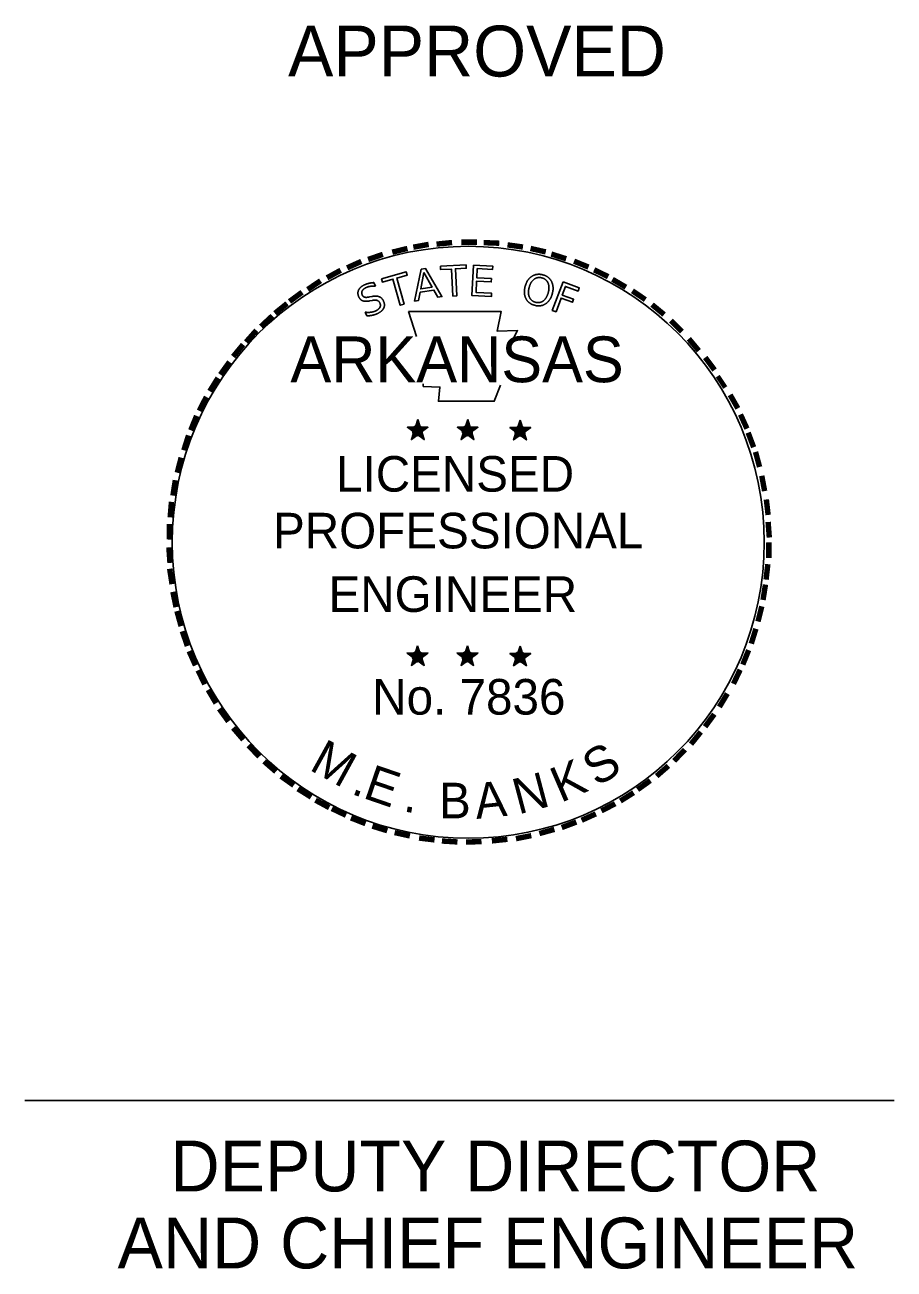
# Model space of a CAD drawing. Extents: x -0.68 to 1.92, y 0 to 0.95.
# Drawn here: x 1.7484 to 1.9193, y 0.0415 to 0.2862 of the extents above; entities that cross this region are included whole.
import ezdxf

# ---------------------------------------------------------------- set-up
doc = ezdxf.new("R2010")
doc.units = 0
doc.layers.add('SHET_Stamp-PE-Chief-Eng', color=7, linetype='Continuous')

msp = doc.modelspace()

# ---------------------------------------------------------------- linework, layer by layer
at = {"layer": 'SHET_Stamp-PE-Chief-Eng'}
for p, q in [((1.81706, 0.23552), (1.81734, 0.23483)), ((1.85009, 0.23645), (1.85009, 0.23645)), ((1.85025, 0.23705), (1.85025, 0.23705)), ((1.81617, 0.23269), (1.81666, 0.23279)), ((1.81673, 0.23202), (1.81623, 0.23192)), ((1.81562, 0.22896), (1.81532, 0.2297)), ((1.82568, 0.20858), (1.82544, 0.20707)), ((1.82568, 0.20641), (1.82568, 0.20858)), ((1.82568, 0.20858), (1.82598, 0.20713)), ((1.83551, 0.20858), (1.83527, 0.20707)), ((1.83551, 0.20641), (1.83551, 0.20858)), ((1.83551, 0.20858), (1.83576, 0.20713)), ((1.84583, 0.20846), (1.84559, 0.20701)), ((1.84583, 0.20635), (1.84583, 0.20846)), ((1.84583, 0.20846), (1.84608, 0.20701)), ((1.82363, 0.20707), (1.82568, 0.20641)), ((1.82363, 0.20707), (1.82513, 0.20683)), ((1.82363, 0.20707), (1.82501, 0.20635)), ((1.82441, 0.20466), (1.82568, 0.20641)), ((1.82441, 0.20466), (1.82513, 0.20611)), ((1.82441, 0.20466), (1.82562, 0.20593)), ((1.82694, 0.20466), (1.82562, 0.20593)), ((1.82767, 0.20707), (1.82568, 0.20641)), ((1.82694, 0.20466), (1.82568, 0.20641)), ((1.82767, 0.20707), (1.82604, 0.20677)), ((1.82694, 0.20466), (1.8261, 0.20635)), ((1.82767, 0.20707), (1.82652, 0.20647)), ((1.83346, 0.20707), (1.83551, 0.20641)), ((1.83346, 0.20707), (1.83491, 0.20683)), ((1.83346, 0.20707), (1.83479, 0.20635)), ((1.83419, 0.20466), (1.83551, 0.20641)), ((1.83419, 0.20466), (1.83497, 0.20611)), ((1.83419, 0.20466), (1.83545, 0.20593)), ((1.83672, 0.20466), (1.83545, 0.20593)), ((1.83751, 0.20707), (1.83551, 0.20641)), ((1.83672, 0.20466), (1.83551, 0.20641)), ((1.83751, 0.20707), (1.83582, 0.20677)), ((1.83672, 0.20466), (1.83588, 0.20635)), ((1.83751, 0.20707), (1.8363, 0.20647)), ((1.84378, 0.20701), (1.84583, 0.20635)), ((1.84378, 0.20701), (1.84523, 0.20671)), ((1.84378, 0.20701), (1.84517, 0.20629)), ((1.84451, 0.2046), (1.84583, 0.20635)), ((1.84451, 0.2046), (1.84529, 0.20605)), ((1.84451, 0.2046), (1.84583, 0.20587)), ((1.84789, 0.20701), (1.84583, 0.20635)), ((1.84704, 0.2046), (1.84583, 0.20635)), ((1.84704, 0.2046), (1.84583, 0.20587)), ((1.84789, 0.20701), (1.84614, 0.20671)), ((1.84704, 0.2046), (1.84626, 0.20629)), ((1.84789, 0.20701), (1.84662, 0.20641)), ((1.82562, 0.1641), (1.82538, 0.16266)), ((1.82562, 0.16199), (1.82562, 0.1641)), ((1.82562, 0.1641), (1.82592, 0.16266)), ((1.83545, 0.1641), (1.83521, 0.16266)), ((1.83545, 0.16199), (1.83545, 0.1641)), ((1.83545, 0.1641), (1.8357, 0.16266)), ((1.84583, 0.16404), (1.84559, 0.1626)), ((1.84583, 0.16193), (1.84583, 0.16404)), ((1.84583, 0.16404), (1.84608, 0.1626)), ((1.82357, 0.16266), (1.82562, 0.16199)), ((1.82357, 0.16266), (1.82513, 0.16235)), ((1.82357, 0.16266), (1.82501, 0.16193)), ((1.82441, 0.16024), (1.82562, 0.16199)), ((1.82441, 0.16024), (1.82513, 0.16169)), ((1.82441, 0.16024), (1.82562, 0.16157)), ((1.82767, 0.16266), (1.82562, 0.16199)), ((1.82694, 0.16024), (1.82562, 0.16199)), ((1.82694, 0.16024), (1.82562, 0.16151)), ((1.82767, 0.16266), (1.82598, 0.16235)), ((1.82694, 0.16024), (1.8261, 0.16193)), ((1.82767, 0.16266), (1.82652, 0.16205)), ((1.8334, 0.16266), (1.83545, 0.16199)), ((1.8334, 0.16266), (1.83491, 0.16235)), ((1.8334, 0.16266), (1.83479, 0.16193)), ((1.83419, 0.16024), (1.83545, 0.16199)), ((1.83419, 0.16024), (1.83491, 0.16169)), ((1.83419, 0.16024), (1.83545, 0.16157)), ((1.83751, 0.16266), (1.83545, 0.16199)), ((1.83666, 0.16024), (1.83545, 0.16199)), ((1.83666, 0.16024), (1.83545, 0.16151)), ((1.83751, 0.16266), (1.83576, 0.16235)), ((1.83666, 0.16024), (1.83588, 0.16193)), ((1.83751, 0.16266), (1.83624, 0.16205)), ((1.84378, 0.1626), (1.84583, 0.16193)), ((1.84378, 0.1626), (1.84523, 0.16229)), ((1.84378, 0.1626), (1.84517, 0.16187)), ((1.84451, 0.16018), (1.84583, 0.16193)), ((1.84451, 0.16018), (1.84529, 0.16163)), ((1.84451, 0.16018), (1.84583, 0.16151)), ((1.84789, 0.1626), (1.84583, 0.16193)), ((1.84704, 0.16018), (1.84583, 0.16193)), ((1.84789, 0.1626), (1.84614, 0.16229)), ((1.84704, 0.16018), (1.8462, 0.16187)), ((1.84789, 0.1626), (1.84662, 0.16199)), ((1.84704, 0.16018), (1.84583, 0.16145)), ((1.74841, 0.07469), (1.91934, 0.07469))]:
    msp.add_line(p, q, dxfattribs=at)
for points in [[(1.81855, 0.23625), (1.82342, 0.23762), (1.82359, 0.237), (1.82153, 0.23642), (1.82298, 0.23129), (1.82223, 0.23108), (1.82078, 0.23621), (1.81873, 0.23563)], [(1.82632, 0.23814), (1.82504, 0.23187), (1.82584, 0.232), (1.82613, 0.23361), (1.82884, 0.23406), (1.82964, 0.23263), (1.83043, 0.23276), (1.82721, 0.23829)], [(1.82688, 0.2375), (1.8285, 0.23465), (1.82626, 0.23428)], [(1.83012, 0.23872), (1.83516, 0.23899), (1.8352, 0.23835), (1.83306, 0.23823), (1.83335, 0.23291), (1.83258, 0.23286), (1.83229, 0.23819), (1.83015, 0.23807)], [(1.83664, 0.23896), (1.8404, 0.23876), (1.84037, 0.23811), (1.83738, 0.23827), (1.83729, 0.23645), (1.84015, 0.2363), (1.84011, 0.23566), (1.83725, 0.23581), (1.83714, 0.23359), (1.8402, 0.23343), (1.84016, 0.23278), (1.83633, 0.23298)], [(1.85423, 0.23566), (1.85743, 0.23446), (1.8572, 0.23385), (1.85472, 0.23478), (1.85409, 0.23308), (1.85632, 0.23225), (1.8561, 0.23164), (1.85386, 0.23248), (1.85286, 0.22979), (1.85213, 0.23006)]]:
    msp.add_lwpolyline(points, close=True, dxfattribs=at)
for points in [[(1.82387, 0.22982), (1.82544, 0.22494)], [(1.84445, 0.22445), (1.84529, 0.22608), (1.84131, 0.22596), (1.84209, 0.22982), (1.82387, 0.22982)], [(1.82676, 0.21564), (1.82676, 0.2151), (1.83002, 0.21498), (1.82972, 0.2122), (1.8407, 0.2122), (1.84191, 0.21534)], [(1.82568, 0.20858), (1.82694, 0.20466), (1.82363, 0.20707), (1.82767, 0.20707), (1.82441, 0.20466), (1.82568, 0.20858)], [(1.83551, 0.20858), (1.83672, 0.20466), (1.83346, 0.20707), (1.83751, 0.20707), (1.83419, 0.20466), (1.83551, 0.20858)], [(1.84583, 0.20846), (1.84704, 0.2046), (1.84378, 0.20701), (1.84789, 0.20701), (1.84451, 0.2046), (1.84583, 0.20846)], [(1.82562, 0.1641), (1.82694, 0.16024), (1.82357, 0.16266), (1.82767, 0.16266), (1.82441, 0.16024), (1.82562, 0.1641)], [(1.83545, 0.1641), (1.83666, 0.16024), (1.8334, 0.16266), (1.83751, 0.16266), (1.83419, 0.16024), (1.83545, 0.1641)], [(1.84583, 0.16404), (1.84704, 0.16018), (1.84378, 0.1626), (1.84789, 0.1626), (1.84451, 0.16018), (1.84583, 0.16404)]]:
    msp.add_lwpolyline(points, dxfattribs=at)
for centre, radius in [((1.8356, 0.18445), 0.05821), ((1.82562, 0.2064), 0.00101), ((1.82562, 0.2064), 0.000848), ((1.82562, 0.2064), 0.000679), ((1.82562, 0.2064), 0.000581), ((1.82562, 0.2064), 0.000438), ((1.82562, 0.2064), 0.000291), ((1.82562, 0.2064), 0.000174), ((1.83542, 0.2064), 0.00101), ((1.83542, 0.2064), 0.000848), ((1.83542, 0.2064), 0.000679), ((1.83542, 0.2064), 0.000581), ((1.83542, 0.2064), 0.000438), ((1.83542, 0.2064), 0.000291), ((1.83542, 0.2064), 0.000174), ((1.84577, 0.20633), 0.00101), ((1.84577, 0.20633), 0.000848), ((1.84577, 0.20633), 0.000679), ((1.84577, 0.20633), 0.000581), ((1.84577, 0.20633), 0.000438), ((1.84577, 0.20633), 0.000291), ((1.84577, 0.20633), 0.000174), ((1.8256, 0.16198), 0.00101), ((1.8256, 0.16198), 0.000848), ((1.8256, 0.16198), 0.000679), ((1.8256, 0.16198), 0.000581), ((1.8256, 0.16198), 0.000438), ((1.8256, 0.16198), 0.000291), ((1.8256, 0.16198), 0.000174), ((1.83539, 0.16198), 0.00101), ((1.83539, 0.16198), 0.000848), ((1.83539, 0.16198), 0.000679), ((1.83539, 0.16198), 0.000581), ((1.83539, 0.16198), 0.000438), ((1.83539, 0.16198), 0.000291), ((1.83539, 0.16198), 0.000174), ((1.84575, 0.16192), 0.00101), ((1.84575, 0.16192), 0.000848), ((1.84575, 0.16192), 0.000679), ((1.84575, 0.16192), 0.000581), ((1.84575, 0.16192), 0.000438), ((1.84575, 0.16192), 0.000291), ((1.84575, 0.16192), 0.000174)]:
    msp.add_circle(centre, radius, dxfattribs=at)
for points in [[(1.81408, 0.23414), (1.81442, 0.23477), (1.81533, 0.23514)], [(1.81533, 0.23514), (1.81572, 0.2353), (1.81616, 0.2354)], [(1.81616, 0.2354), (1.81659, 0.23549), (1.81706, 0.23552)], [(1.84809, 0.23675), (1.84714, 0.23613), (1.84678, 0.23475)], [(1.84757, 0.23455), (1.84786, 0.23566), (1.84854, 0.23617)], [(1.85025, 0.23705), (1.84903, 0.23737), (1.84809, 0.23675)], [(1.84854, 0.23617), (1.84923, 0.23668), (1.85009, 0.23645)], [(1.85009, 0.23645), (1.85096, 0.23622), (1.85129, 0.23544)], [(1.85198, 0.23572), (1.85147, 0.23673), (1.85025, 0.23705)], [(1.85129, 0.23544), (1.85163, 0.23466), (1.85133, 0.23355)], [(1.85213, 0.23334), (1.85249, 0.23471), (1.85198, 0.23572)], [(1.81404, 0.23278), (1.81374, 0.23351), (1.81408, 0.23414)], [(1.81481, 0.23195), (1.81429, 0.23215), (1.81404, 0.23278)], [(1.81479, 0.23397), (1.81455, 0.23359), (1.81473, 0.23313)], [(1.81473, 0.23313), (1.81489, 0.23275), (1.81519, 0.23266)], [(1.81565, 0.2346), (1.81503, 0.23435), (1.81479, 0.23397)], [(1.81519, 0.23266), (1.8155, 0.23256), (1.81617, 0.23269)], [(1.81643, 0.2348), (1.81601, 0.23475), (1.81565, 0.2346)], [(1.81734, 0.23483), (1.81686, 0.23486), (1.81643, 0.2348)], [(1.81666, 0.23279), (1.81757, 0.23297), (1.81813, 0.23273)], [(1.81813, 0.23273), (1.81869, 0.23249), (1.81896, 0.23182)], [(1.84678, 0.23475), (1.84641, 0.23338), (1.84693, 0.23238)], [(1.84762, 0.23266), (1.84728, 0.23344), (1.84757, 0.23455)], [(1.84882, 0.23165), (1.84796, 0.23188), (1.84762, 0.23266)], [(1.85133, 0.23355), (1.85104, 0.23244), (1.85036, 0.23193)], [(1.85082, 0.23135), (1.85176, 0.23197), (1.85213, 0.23334)], [(1.81623, 0.23192), (1.81533, 0.23174), (1.81481, 0.23195)], [(1.81771, 0.23201), (1.81736, 0.23214), (1.81673, 0.23202)], [(1.81728, 0.2299), (1.81793, 0.23017), (1.81818, 0.23058)], [(1.81892, 0.23039), (1.81855, 0.22976), (1.81751, 0.22933)], [(1.81824, 0.23146), (1.81806, 0.23188), (1.81771, 0.23201)], [(1.81818, 0.23058), (1.81843, 0.23098), (1.81824, 0.23146)], [(1.81896, 0.23182), (1.81929, 0.23102), (1.81892, 0.23039)], [(1.84693, 0.23238), (1.84744, 0.23137), (1.84866, 0.23105)], [(1.84866, 0.23105), (1.84988, 0.23073), (1.85082, 0.23135)], [(1.85036, 0.23193), (1.84969, 0.23142), (1.84882, 0.23165)], [(1.81532, 0.2297), (1.81585, 0.22963), (1.81635, 0.22968)], [(1.81664, 0.22908), (1.81616, 0.22899), (1.81562, 0.22896)], [(1.81635, 0.22968), (1.81685, 0.22973), (1.81728, 0.2299)], [(1.81751, 0.22933), (1.81712, 0.22917), (1.81664, 0.22908)]]:
    msp.add_open_spline(points, degree=2, dxfattribs=at)

# ---------------------------------------------------------------- texts
for s, height, p in [('APPROVED', 0.01, (1.80016, 0.27605)), ('ARKANSAS', 0.009, (1.80063, 0.21593)), ('LICENSED', 0.007, (1.8096, 0.19441)), ('PROFESSIONAL', 0.007, (1.79721, 0.18325)), ('ENGINEER', 0.007, (1.80812, 0.17076)), ('No. 7836', 0.007, (1.81672, 0.15057)), ('DEPUTY DIRECTOR', 0.01, (1.77705, 0.0568)), ('AND CHIEF ENGINEER', 0.01, (1.76664, 0.04167))]:
    msp.add_text(s, height=height, dxfattribs=at).set_placement(p)
for s, height, rotation, p in [('-', 0.00939, 13.6301, (1.82097, 0.23785)), ('-', 0.00939, 10.2193, (1.82489, 0.23882)), ('-', 0.00939, 5.8968, (1.82918, 0.23942)), ('-', 0.00939, 0.1862, (1.8337, 0.23984)), ('-', 0.00939, 357.743, (1.83793, 0.23978)), ('-', 0.00939, 352.1617, (1.84227, 0.23942)), ('-', 0.00939, 347.2049, (1.8465, 0.23882)), ('-', 0.00939, 24.3072, (1.81276, 0.23489)), ('-', 0.00939, 19.1761, (1.81657, 0.23646)), ('-', 0.00939, 342.3362, (1.8503, 0.23785)), ('-', 0.00939, 337.8551, (1.85452, 0.23658)), ('-', 0.00939, 28.7918, (1.80908, 0.23302)), ('-', 0.00939, 334.1211, (1.85827, 0.23501)), ('-', 0.00939, 34.0636, (1.80558, 0.23085)), ('-', 0.00939, 329.6409, (1.86164, 0.23332)), ('-', 0.00939, 36.2317, (1.80214, 0.22856)), ('-', 0.00939, 325.8627, (1.86539, 0.23121)), ('-', 0.00938, 38.9507, (1.79943, 0.22632)), ('-', 0.00939, 320.5297, (1.86901, 0.22874)), ('-', 0.00939, 42.9622, (1.79689, 0.22385)), ('-', 0.00939, 315.5786, (1.87251, 0.22584)), ('-', 0.00939, 48.4231, (1.79424, 0.22101)), ('-', 0.00939, 50.6142, (1.79182, 0.21824)), ('-', 0.00939, 309.8797, (1.87583, 0.22258)), ('-', 0.00939, 54.2325, (1.78947, 0.21486)), ('-', 0.00939, 306.6522, (1.87896, 0.21908)), ('-', 0.00938, 58.0706, (1.78754, 0.21178)), ('-', 0.00821, 303.6753, (1.88174, 0.21576)), ('-', 0.00939, 62.8713, (1.78567, 0.20816)), ('-', 0.00939, 299.6684, (1.88367, 0.21214)), ('-', 0.00938, 67.7743, (1.78416, 0.2046)), ('-', 0.00939, 294.6628, (1.8856, 0.20858)), ('-', 0.00939, 72.3945, (1.78295, 0.20092)), ('-', 0.00939, 290.5728, (1.88705, 0.20526)), ('-', 0.00939, 75.461, (1.78174, 0.19669)), ('-', 0.00939, 285.1233, (1.88844, 0.20182)), ('-', 0.00939, 81.2013, (1.78102, 0.19253)), ('-', 0.00939, 280.5493, (1.88965, 0.19742)), ('-', 0.00939, 85.1863, (1.78054, 0.18849)), ('-', 0.00939, 276.5962, (1.89055, 0.19301)), ('-', 0.00939, 274.3301, (1.89091, 0.18873)), ('-', 0.00939, 89.0622, (1.78042, 0.18438)), ('-', 0.00939, 269.9407, (1.89109, 0.18498)), ('-', 0.00939, 94.1959, (1.7806, 0.1801)), ('-', 0.00939, 98.9479, (1.78102, 0.17623)), ('-', 0.00939, 263.5172, (1.89097, 0.18112)), ('-', 0.00939, 260.9953, (1.89055, 0.17726)), ('-', 0.00939, 101.7149, (1.7818, 0.17189)), ('-', 0.00939, 255.7626, (1.88995, 0.17328)), ('-', 0.00939, 105.4578, (1.78277, 0.16839)), ('-', 0.00939, 109.0874, (1.78398, 0.16471)), ('-', 0.00939, 252.8681, (1.88886, 0.16905)), ('-', 0.00938, 114.0643, (1.78549, 0.16121)), ('-', 0.00939, 247.8887, (1.88759, 0.16513)), ('-', 0.00939, 115.7289, (1.7873, 0.15759)), ('-', 0.00939, 244.6197, (1.88603, 0.16145)), ('-', 0.00939, 120.4471, (1.78941, 0.15415)), ('-', 0.00938, 239.0712, (1.88373, 0.15704)), ('-', 0.00939, 125.8934, (1.7917, 0.15089)), ('-', 0.00939, 233.8452, (1.88138, 0.15324)), ('-', 0.00939, 130.7181, (1.79448, 0.14757)), ('-', 0.00939, 231.2538, (1.87884, 0.14986)), ('-', 0.00939, 134.2238, (1.7975, 0.14443)), ('M', 0.007, 331.1686, (1.80412, 0.13982)), ('S', 0.007, 31.466, (1.86088, 0.13627)), ('-', 0.00938, 225.7653, (1.87601, 0.1466)), ('-', 0.00939, 138.9338, (1.80057, 0.14172)), ('E', 0.007, 341.04, (1.81467, 0.13424)), ('K', 0.007, 23.3052, (1.85378, 0.13317)), ('-', 0.00939, 221.0851, (1.87299, 0.14359)), ('-', 0.00939, 144.6463, (1.80383, 0.1393)), ('B', 0.007, 359.9662, (1.82985, 0.13017)), ('A', 0.007, 6.0117, (1.8372, 0.13003)), ('N', 0.007, 14.8189, (1.84544, 0.1309)), ('-', 0.00939, 215.7363, (1.86973, 0.14087)), ('-', 0.00939, 148.0898, (1.80709, 0.13713)), ('.', 0.007, 341.04, (1.81238, 0.13503)), ('-', 0.00939, 212.2491, (1.86665, 0.13858)), ('-', 0.00939, 151.5704, (1.81047, 0.1352)), ('-', 0.00939, 154.6002, (1.81361, 0.13381)), ('.', 0.007, 350.6464, (1.82267, 0.13156)), ('-', 0.00939, 207.3568, (1.86333, 0.13653)), ('-', 0.00939, 158.5612, (1.81723, 0.1323)), ('-', 0.00939, 200.7184, (1.85609, 0.13303)), ('-', 0.00939, 204.2516, (1.85971, 0.13459)), ('-', 0.00939, 162.7983, (1.82127, 0.13103)), ('-', 0.00939, 167.5555, (1.82544, 0.13013)), ('-', 0.00939, 191.2858, (1.84783, 0.13043)), ('-', 0.00939, 195.4743, (1.85211, 0.13164)), ('-', 0.00939, 173.1155, (1.82996, 0.12946)), ('-', 0.00939, 176.5183, (1.83425, 0.12911)), ('-', 0.00939, 181.5918, (1.83866, 0.12923)), ('-', 0.00939, 185.8167, (1.84348, 0.12971))]:
    msp.add_text(s, height=height, rotation=rotation, dxfattribs=at).set_placement(p)

doc.saveas('drawing.dxf')
